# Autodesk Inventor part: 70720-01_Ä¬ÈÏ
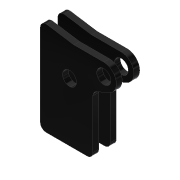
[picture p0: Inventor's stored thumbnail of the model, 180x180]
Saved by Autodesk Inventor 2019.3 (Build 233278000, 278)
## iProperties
Created: 2010-06
Part Number: 70720-01_Ä¬ÈÏ
Material: Ogólny
Document SubType Name: Modeling
Designer: CADENGINEERING4
Density: 1 g/cm^3
Appearance: Gładki — czarny
Author: CADENGINEERING4
Revision Number: ÈÎºÎ
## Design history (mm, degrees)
feature "NONE"
feature "NONE:1"
node "Bryła1"
node "Bryła2"
